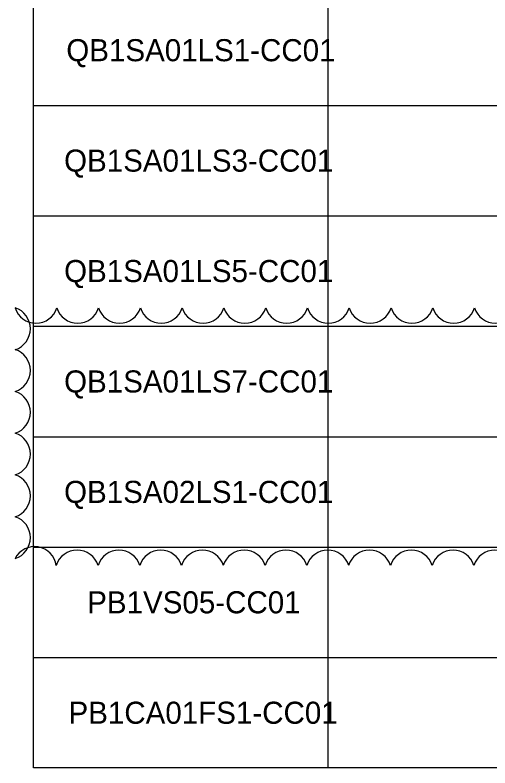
# Model space of a CAD drawing. Extents: x 0 to 841, y 0 to 594.
# Drawn here: x 517.5 to 582, y 190 to 292.3 of the extents above; entities that cross this region are included whole.
import ezdxf

# ---------------------------------------------------------------- set-up
doc = ezdxf.new("R2010")
doc.units = 0
doc.layers.add('INSTALLED', color=7, linetype='Continuous')
doc.layers.add('Level 1', color=7, linetype='Continuous')

msp = doc.modelspace()

# ---------------------------------------------------------------- linework, layer by layer
at = {"layer": 'INSTALLED'}
for p, q in [((560, 560), (560, 190)), ((520, 280), (810, 280)), ((520, 265), (810, 265)), ((520, 250), (810, 250)), ((520, 235), (810, 235)), ((520, 220), (810, 220)), ((520, 205), (810, 205))]:
    msp.add_line(p, q, dxfattribs=at)
msp.add_lwpolyline([(520, 560), (810, 560), (810, 190), (520, 190)], close=True, dxfattribs=at)
at = {"layer": 'Level 1'}
for centre, radius, start, end in [((520.34, 253.39), 2.98, 197.5, 342.5), ((516.61, 249.66), 2.98, 287.5, 72.5), ((526.01, 253.39), 2.98, 197.5, 342.5), ((531.69, 253.39), 2.98, 197.5, 342.5), ((537.36, 253.39), 2.98, 197.5, 342.5), ((543.04, 253.39), 2.98, 197.5, 342.5), ((548.71, 253.39), 2.98, 197.5, 342.5), ((554.39, 253.39), 2.98, 197.5, 342.5), ((560.06, 253.39), 2.98, 197.5, 342.5), ((565.73, 253.39), 2.98, 197.5, 342.5), ((571.41, 253.39), 2.98, 197.5, 342.5), ((577.08, 253.39), 2.98, 197.5, 342.5), ((582.76, 253.39), 2.98, 197.5, 342.5), ((516.61, 243.99), 2.98, 287.5, 72.5), ((516.61, 238.31), 2.98, 287.5, 72.5), ((516.61, 232.64), 2.98, 287.5, 72.5), ((516.61, 226.96), 2.98, 287.5, 72.5), ((516.61, 221.29), 2.98, 287.5, 72.5), ((520.15, 217.09), 2.97, 7.8392, 152.8392), ((525.93, 216.61), 2.98, 17.5, 162.5), ((531.61, 216.61), 2.98, 17.5, 162.5), ((537.28, 216.61), 2.98, 17.5, 162.5), ((542.95, 216.61), 2.98, 17.5, 162.5), ((548.63, 216.61), 2.98, 17.5, 162.5), ((554.3, 216.61), 2.98, 17.5, 162.5), ((559.98, 216.61), 2.98, 17.5, 162.5), ((565.65, 216.61), 2.98, 17.5, 162.5), ((571.33, 216.61), 2.98, 17.5, 162.5), ((577, 216.61), 2.98, 17.5, 162.5), ((582.68, 216.61), 2.98, 17.5, 162.5)]:
    msp.add_arc(centre, radius, start, end, dxfattribs=at)

# ---------------------------------------------------------------- texts
at = {"layer": 'INSTALLED'}
for s, p in [('QB1SA01LS1-CC01', (524.46, 286)), ('QB1SA01LS3-CC01', (524.16, 271)), ('QB1SA01LS5-CC01', (524.16, 256)), ('QB1SA01LS7-CC01', (524.16, 241)), ('QB1SA02LS1-CC01', (524.16, 226)), ('PB1VS05-CC01', (527.3, 211)), ('PB1CA01FS1-CC01', (524.76, 196))]:
    msp.add_text(s, height=3, dxfattribs=at).set_placement(p)

doc.saveas('drawing.dxf')
